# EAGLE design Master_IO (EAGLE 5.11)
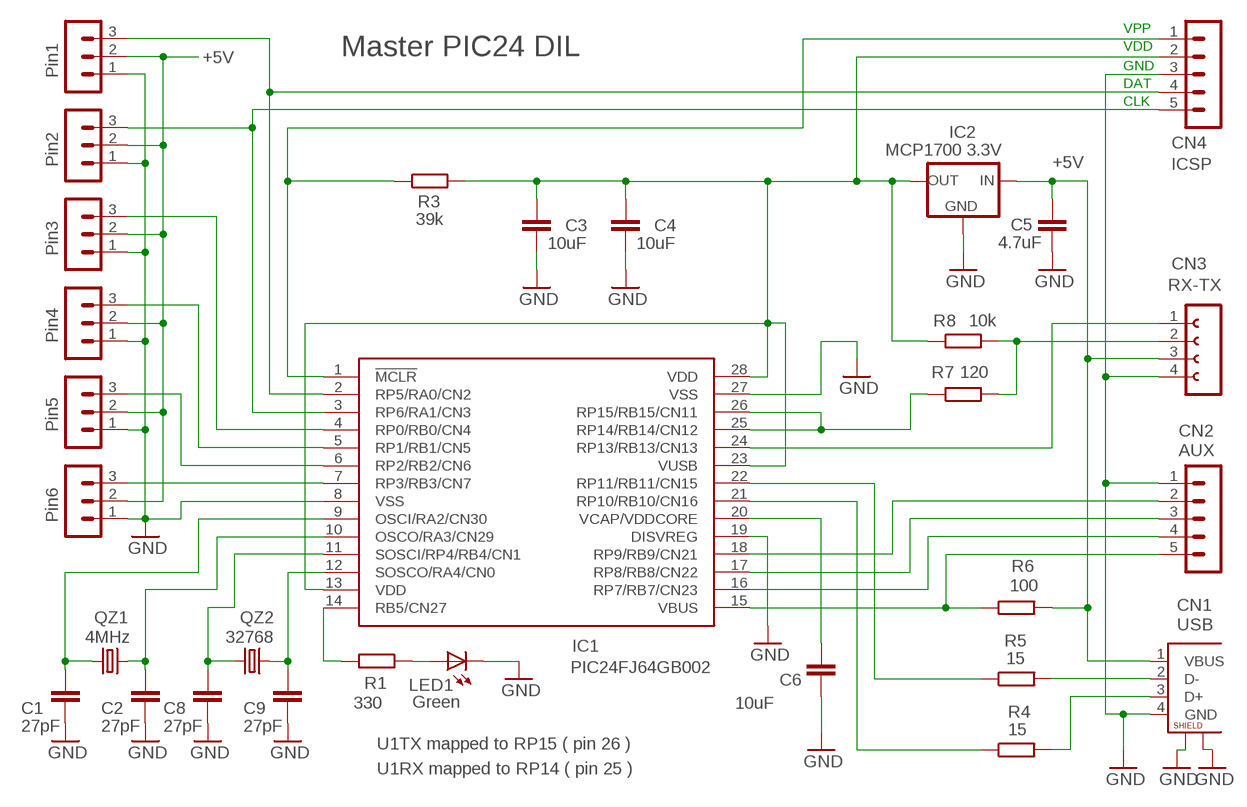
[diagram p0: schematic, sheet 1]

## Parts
C1  27pF  C-EUC0805  [C0805]
C2  27pF  C-EUC0805  [C0805]
C3  10uF  C-EUC0603  [C0603]
C4  10uF  C-EUC0603  [C0603]
C5  4.7uF  C-EUC0603  [C0603]
C6  10uF  C-EUC0603  [C0603]
C8  27pF  C-EUC0805  [C0805]
C9  27pF  C-EUC0805  [C0805]
CN1  USB  USB-B  [USB-B-LARGE]
CN2  AUX  MA05-1  [MA05-1]
CN3  RX-TX  FE04-1  [FE04-1]
CN4  ICSP  MA05-1W  [MA05-1W]
IC1  PIC24FJ64GB002  [DIL28-3]
IC2  MCP1700 3.3V  MCP1700L1  [TO92L1]
LED1  Green  LED3MM_F  [LED3MM]
QZ1  4MHz  CRYSTALHC49U70  [HC49U70]
QZ2  32768  CRYSTALTC26H  [TC26H]
R1  330  R-EU_R0805  [R0805]
R3  39k  R-EU_R0805  [R0805]
R4  15  R-EU_R0805  [R0805]
R5  15  R-EU_R0805  [R0805]
R6  100  R-EU_0204/7  [0204/7]
R7  120  R-EU_R0805  [R0805]
R8  10k  R-EU_R0805  [R0805]
SV1  Pin1  MA03-1L1  [MA03-1_L1]
SV2  Pin2  MA03-1L1  [MA03-1_L1]
SV3  Pin3  MA03-1L1  [MA03-1_L1]
SV4  Pin4  MA03-1L1  [MA03-1_L1]
SV5  Pin5  MA03-1L1  [MA03-1_L1]
SV6  Pin6  MA03-1L1  [MA03-1_L1]

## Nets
+5V: C5.1 CN1.1(VBUS) CN3.3 IC2.2(IN) R6.2 SV1.2 SV2.2 SV3.2 SV4.2 SV5.2 SV6.2
GND: C1.2 C2.1 C3.2 C4.2 C5.2 C6.2 C8.2 C9.1 CN1.4(GND) CN1.G1 CN1.G2 CN2.1 CN3.4 CN4.3 IC1.8(VSS) IC1.19(DISVREG) IC1.27(VSS) IC2.3(GND) LED1.K(C) SV1.1 SV2.1 SV3.1 SV4.1 SV5.1 SV6.1
N$1: CN4.1 IC1.1(!MCLR) R3.1
N$2: CN4.4 IC1.2(RP5/RA0/CN2) SV1.3
N$3: IC1.21(RP10/RB10/CN16) R4.1
N$4: CN1.2(D-) R5.2
N$6: CN4.5 IC1.3(RP6/RA1/CN3) SV2.3
N$7: IC1.22(RP11/RB11/CN15) R5.1
N$8: LED1.A R1.1
N$9: CN2.4 IC1.16(RP7/RB7/CN23)
N$10: C9.2 IC1.12(SOSCO/RA4/CN0) QZ2.1
N$11: IC1.25(RP14/RB14/CN12) IC1.26(RP15/RB15/CN11) R7.1
N$12: CN2.3 IC1.17(RP8/RB8/CN22)
N$13: CN1.3(D+) R4.2
N$14: CN2.2 IC1.18(RP9/RB9/CN21)
N$15: CN3.2 R7.2 R8.2
N$16: C2.2 IC1.10(OSCO/RA3/CN29) QZ1.2
N$17: C1.1 IC1.9(OSCI/RA2/CN30) QZ1.1
N$18: CN3.1 IC1.24(RP13/RB13/CN13)
N$19: IC1.7(RP3/RB3/CN7) SV6.3
N$20: IC1.6(RP2/RB2/CN6) SV5.3
N$21: IC1.5(RP1/RB1/CN5) SV4.3
N$22: IC1.4(RP0/RB0/CN4) SV3.3
N$24: C8.1 IC1.11(SOSCI/RP4/RB4/CN1) QZ2.2
N$28: IC1.14(RB5/CN27) R1.2
VBUS: CN2.5 IC1.15(VBUS) R6.1
VCAP/VDDCORE: C6.1 IC1.20(VCAP/VDDCORE)
VDD: C3.1 C4.1 CN4.2 IC1.13(VDD) IC1.23(VUSB) IC1.28(VDD) IC2.1(OUT) R3.2 R8.1

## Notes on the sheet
- VPP
- VDD
- Master PIC24 DIL
- GND
- DAT
- CLK
- U1TX mapped to RP15 ( pin 26 )
- U1RX mapped to RP14 ( pin 25 )

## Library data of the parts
C1-C6 C8 C9 = 00-LIVIO:C-EU: CAPACITOR, European symbol
CN1 = 03-Comp-Livio:USB-B: USB Type-B Connector
CN2 = 03-con-lstb-M:MA05-1: PIN HEADER
CN3 = 01-con-lsta:FE04-1: FEMALE HEADER
CN4 = con-lstb:MA05-1W
IC1 = 00-LIVIO:PIC24FJ64GB002: PIC24FJ64GA002 edit this description Auto generated by make-symbol-device-package-bsdl.ulp Rev. 25 Source: PIC24FJ64GA002.bsd
IC2 = 00-LIVIO:MCP1700: Linear regulator Quescient courrent 1.8uA Input 2.3v to 6v Output 1.2v 1.8v 2.5v 3.0v 3.3v 5.0v
LED1 = 03-Comp-Livio:LED: Questi ed (in versione da 3 e 5mm) hanno due piazzole SMD e anche i fori.
QZ1 QZ2 = 00-LIVIO:CRYSTAL: CRYSTAL
R1 R3-R8 = 00-LIVIO:R-EU_: RESISTOR, European symbol
SV1-SV6 = 03-con-lstb-M:MA03-1: PIN HEADER

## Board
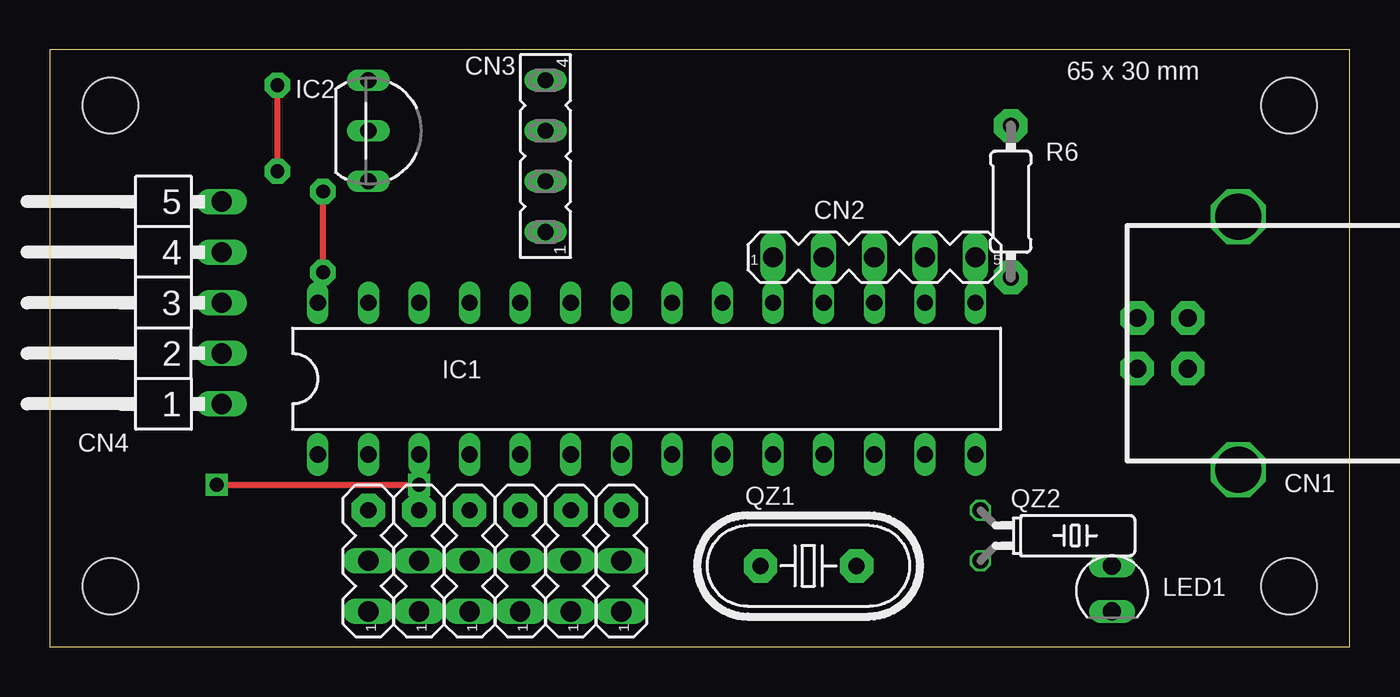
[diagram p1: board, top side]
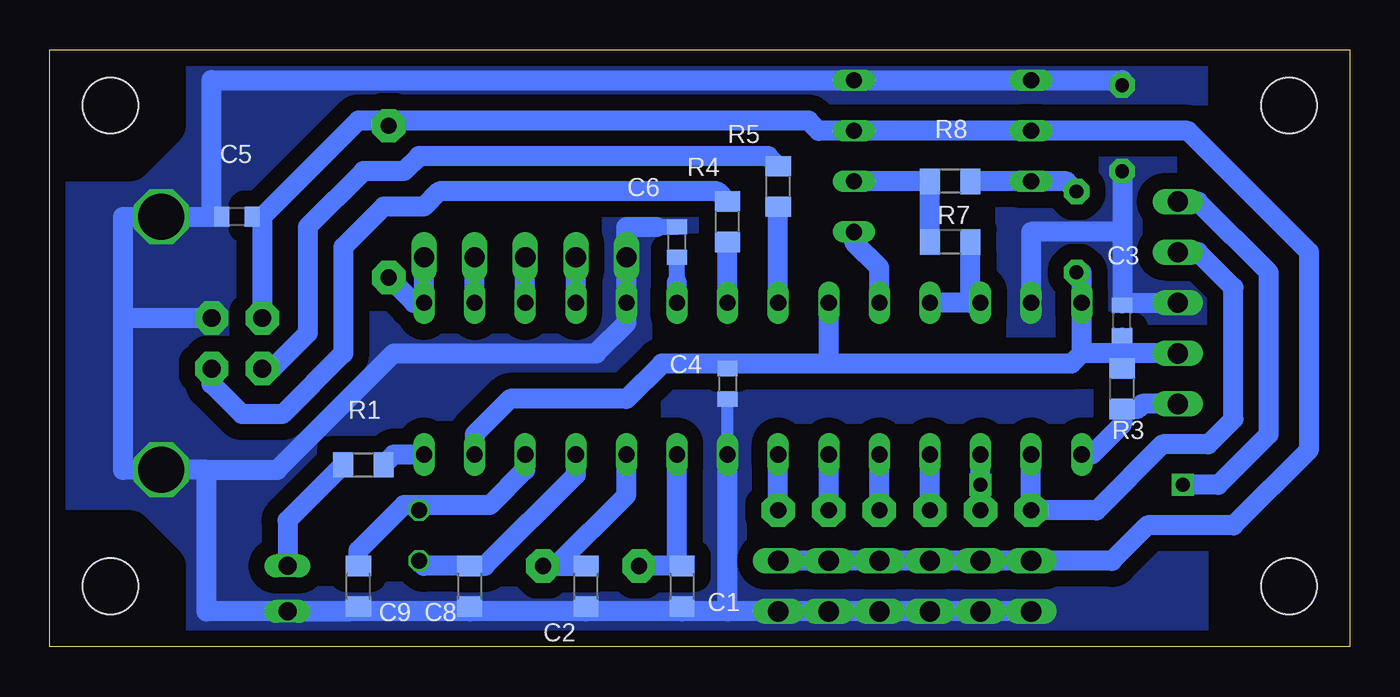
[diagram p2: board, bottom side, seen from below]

Size 65.28 x 29.97 mm. Coordinates in mm from the lower left corner, seen from the top.
Outline: 0,0 65.28,0 65.28,29.97 0,29.97 0,0
Copper layers (1*16): Top 0.035mm / dielectric 1.5mm / Bottom 0.035mm
Design rules "FastGcode-DesignRules": minimum track width 10mil, minimum drill 27mil, track to track 27mil, track to pad 27mil, pad to pad 27mil, via to via 27mil, smd to smd 27mil, copper to edge 27mil, drill to drill 8mil, minimum pad ring 5mil, minimum via ring 8mil, stop-mask expansion 4mil, vias tented up to drill 0mil, thermal gap 41mil
Holes 2.8 mm at 62.23,27.18 62.23,3.05 3.05,27.18 3.05,3.05
bRestrict: 8 lines

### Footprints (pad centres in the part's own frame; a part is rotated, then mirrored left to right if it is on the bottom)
C0805 = smd 1.016 x 1.27: 1 -1.016,0; 2 1.016,0
C0603 = smd 0.762 x 1.016: 1 -0.762,0; 2 0.762,0
USB-B-LARGE = drill 0.9 pad 1.676 octagon: 1 1.27,5.08; 2 -1.27,5.08; 3 -1.27,2.54; 4 1.27,2.54 | drill 2.3 octagon: G1 -6.35,0; G2 6.35,0
MA05-1 = drill 1.016 long: 1 -5.08,0; 2 -2.54,0; 3 0,0; 4 2.54,0; 5 5.08,0
FE04-1 = drill 0.813 long: 1 -3.81,0; 2 -1.27,0; 3 1.27,0; 4 3.81,0
MA05-1W = drill 1.016 long: 1 -5.08,0; 2 -2.54,0; 3 0,0; 4 2.54,0; 5 5.08,0
DIL28-3 = drill 0.813 long: 1 -16.51,-3.81; 2 -13.97,-3.81; 3 -11.43,-3.81; 4 -8.89,-3.81; 5 -6.35,-3.81; 6 -3.81,-3.81; 7 -1.27,-3.81; 8 1.27,-3.81; 9 3.81,-3.81; 10 6.35,-3.81; 11 8.89,-3.81; 12 11.43,-3.81; 13 13.97,-3.81; 14 16.51,-3.81; 15 16.51,3.81; 16 13.97,3.81; 17 11.43,3.81; 18 8.89,3.81; 19 6.35,3.81; 20 3.81,3.81; 21 1.27,3.81; 22 -1.27,3.81; 23 -3.81,3.81; 24 -6.35,3.81; 25 -8.89,3.81; 26 -11.43,3.81; 27 -13.97,3.81; 28 -16.51,3.81
TO92L1 = drill 0.813 long: 1 2.54,0; 2 0,0; 3 -2.54,0
LED3MM = drill 0.9 long: A -1.016,0; K 1.27,0
HC49U70 = drill 0.813 pad 1.676 octagon: 1 -2.413,0; 2 2.413,0
TC26H = drill 0.813 octagon: 1 -1.27,0; 2 1.27,0
R0805 = smd 1.016 x 1.27: 1 -1.016,0; 2 1.016,0
0204/7 = drill 0.813 pad 1.676 octagon: 1 -3.81,0; 2 3.81,0
MA03-1_L1 = drill 1.016 long: 1 -2.54,0; 2 0,0 | drill 0.813 pad 1.676 octagon: 3 2.54,0

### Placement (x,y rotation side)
C1  33.53,3.05 270 bottom
C2  38.35,3.05 90 bottom
C3  11.43,16.38 90 bottom
C4  31.24,13.21 270 bottom
C5  55.88,21.59 180 bottom
C6  33.78,20.32 90 bottom
C8  44.2,3.05 270 bottom
C9  49.78,3.05 90 bottom
CN1  59.69,15.24 90 top
CN2  41.4,19.56 0 top
CN3  24.89,24.64 90 top
CN4  8.64,17.27 90 top
IC1  29.97,13.46 0 top
IC2  16,25.91 270 top
LED1  53.34,3.05 270 top
QZ1  38.1,4.06 0 top
QZ2  46.74,5.59 270 top
R1  49.53,9.14 0 bottom
R3  11.43,12.95 90 bottom
R4  31.24,21.34 90 bottom
R5  28.7,23.11 90 bottom
R6  48.26,22.35 90 top
R7  20.07,20.32 180 bottom
R8  20.07,23.37 180 bottom
SV1  16,4.32 90 top
SV2  18.54,4.32 90 top
SV3  21.08,4.32 90 top
SV4  23.62,4.32 90 top
SV5  26.16,4.32 90 top
SV6  28.7,4.32 90 top

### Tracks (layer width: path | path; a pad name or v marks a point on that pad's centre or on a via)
+5V
  Bottom 0.61: 54.61,21.59 C5.1
  Bottom 1.016: SV6.2 SV5.2 SV4.2 SV3.2 SV2.2 SV1.2 11.94,4.32 10.16,6.1 5.84,6.1 2.03,9.91 2.03,19.81 8.13,25.91 IC2.2 CN3.3 26.67,25.91 27.18,26.42 48.51,26.42 | 48.51,26.42 49.78,26.42 54.61,21.59 CN1.1 | 48.51,26.42 R6.2
GND  (via drill 0.7 pad 1.27)
  Top 0.305: v11.43,28.19 v11.43,23.88
  Bottom 0.61: 57.15,21.59 C5.2 | IC1.8 C4.2
  Bottom 0.813: 34.8,21.08 C6.2 | 11.43,17.27 C3.2
  Bottom 1.016: 61.59,16.51 61.59,21.59 CN1.G2 57.15,21.59 57.15,28.45 CN3.4 IC2.3 11.43,28.45 v11.43,28.19 | 61.59,16.51 61.59,8.89 CN1.G1 57.4,8.89 | 31.24,1.78 33.53,1.78 | 61.59,16.51 CN1.4 | 38.35,1.78 C2.1 | 31.24,1.78 IC1.8 | CN4.3 11.43,17.27 11.43,20.83 | LED1.K 57.4,1.78 57.4,8.89 | 33.53,1.78 C1.2 | 38.35,1.78 44.2,1.78 | 44.2,1.78 LED1.K | 33.53,1.78 38.35,1.78 | IC1.19 36.32,16.26 37.85,14.73 48.01,14.73 53.85,8.89 57.4,8.89 | IC1.19 36.32,21.08 34.8,21.08 | SV1.1 SV2.1 SV3.1 SV4.1 SV5.1 SV6.1 31.24,1.78 | IC1.19 CN2.1 | IC1.27 16,20.83 11.43,20.83 | v11.43,23.88 11.43,20.83 | LED1.K 50.29,1.78 50.04,2.03 C9.1 | 44.2,1.78 C8.2
  pour Bottom (isolate 0.8, rank 6, no thermals): -1,-1 66.28,-1 66.28,30.97 -1,30.97
N$1
  Bottom 1.016: IC1.1 12.95,9.65 11.43,11.18 R3.1 10.67,11.94 10.41,12.19 CN4.1
N$2
  Bottom 1.016: IC1.2 SV1.3 12.7,6.86 9.4,10.16 7.11,10.16 5.84,11.43 5.84,18.03 7.62,19.81 CN4.4
N$3
  Bottom 1.016: IC1.21 R4.1
N$4
  Bottom 1.016: CN1.2 54.1,13.97 52.32,15.75 52.32,21.08 49.53,23.88 47.5,23.88 46.74,24.64 29.21,24.64 R5.2
N$6  (via drill 0.7)
  Top 0.305: v8.38,8.13 v18.54,8.13
  Bottom 1.016: CN4.5 7.62,22.35 4.06,18.8 4.06,10.67 6.6,8.13 v8.38,8.13 | SV2.3 v18.54,8.13 IC1.3
N$7
  Bottom 1.016: IC1.22 R5.1
N$8
  Bottom 1.016: R1.1 53.34,6.35 LED1.A
N$9
  Bottom 1.016: IC1.16 CN2.4
N$10
  Bottom 1.016: IC1.12 41.4,8.89 43.18,7.11 46.74,7.11 | 46.74,7.11 47.5,7.11 49.78,4.83 C9.2 | 46.74,7.11 QZ2.1
N$11
  Bottom 1.016: IC1.25 IC1.26 19.05,17.27 R7.1
N$12
  Bottom 1.016: IC1.17 CN2.3
N$13
  Bottom 1.016: CN1.3 57.15,13.21 55.63,11.68 53.59,11.68 50.55,14.73 50.55,20.07 48.51,22.1 46.48,22.1 45.72,22.86 31.75,22.86 R4.2
N$14
  Bottom 1.016: IC1.18 CN2.2
N$15
  Bottom 1.016: CN3.2 R8.2 R7.2
N$16
  Bottom 1.016: C2.2 QZ1.2 39.88,4.06 36.32,7.62 IC1.10
N$17
  Bottom 1.016: C1.1 33.78,4.06 | 33.78,4.06 QZ1.1 | 33.78,4.06 IC1.9
N$18
  Bottom 1.016: IC1.24 23.62,19.05 24.89,20.32 CN3.1
N$19
  Bottom 1.016: SV6.3 IC1.7
N$20
  Bottom 1.016: SV5.3 IC1.6
N$21
  Bottom 1.016: SV4.3 IC1.5
N$22
  Bottom 1.016: SV3.3 IC1.4
N$24
  Bottom 1.016: IC1.11 38.86,8.64 43.43,4.06 C8.1 46.48,4.06 QZ2.2
N$28
  Bottom 1.016: IC1.14 48.01,9.65 R1.2
VBUS
  Bottom 1.016: R6.1 46.99,17.27 IC1.15 CN2.5
VCAP/VDDCORE
  Bottom 0.813: 33.78,18.29 C6.1
  Bottom 1.016: IC1.20 33.78,18.29
VDD  (via drill 0.7 pad 1.27)
  Top 0.305: v13.72,18.8 v13.72,22.86
  Bottom 0.61: 31.24,14.22 C4.1
  Bottom 0.813: 11.43,14.73 C3.1
  Bottom 1.016: 13.46,14.73 13.97,14.22 26.16,14.22 | 26.16,14.22 31.24,14.22 34.54,14.22 36.32,12.45 42.16,12.45 43.94,10.67 IC1.13 | CN4.2 11.43,14.73 | 11.43,14.73 R3.2 | 11.43,14.73 13.46,14.73 | 13.46,14.73 IC1.28 13.46,18.8 v13.72,18.8 | 26.16,14.22 IC1.23 | R8.1 IC2.1 14.22,23.37 v13.72,22.86

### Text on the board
tNames: 65 x 30 mm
